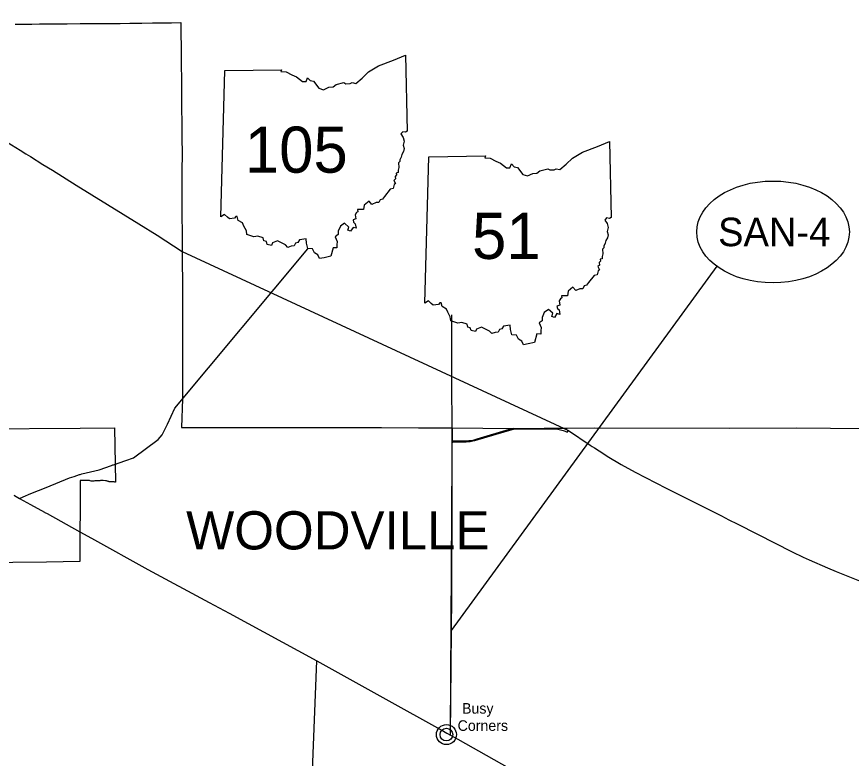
# Model space of a CAD drawing. Extents: x 0 to 798, y 0 to 440.
# Drawn here: x 204.7 to 286.7, y 280.2 to 353 of the extents above; entities that cross this region are included whole.
import ezdxf

# ---------------------------------------------------------------- set-up
doc = ezdxf.new("R2010")
doc.units = 0
for name, color, linetype in [('DV_X_Corp_Line', 7, 'Continuous'), ('GM_X_Corporation_Text', 7, 'Continuous'), ('GM_X_County', 7, 'Continuous'), ('GM_X_Interchange_Ramps', 7, 'Continuous'), ('GM_X_Interstate_Route', 7, 'Continuous'), ('GM_X_State_Route', 7, 'Continuous'), ('GM_X_US_Route', 7, 'Continuous'), ('PV_P_Text', 7, 'Continuous'), ('SH_Data', 7, 'Continuous'), ('SH_Text', 7, 'Continuous')]:
    doc.layers.add(name, color=color, linetype=linetype)

msp = doc.modelspace()

# ---------------------------------------------------------------- linework, layer by layer
at = {"layer": 'DV_X_Corp_Line'}
msp.add_lwpolyline([(200.894, 312.518), (210.921, 312.576), (214.317, 312.612), (214.402, 307.271), (214.372, 307.276), (214.331, 307.284), (214.276, 307.3), (214.135, 307.317), (214.076, 307.308), (214.016, 307.314), (213.964, 307.314), (213.914, 307.31), (213.862, 307.316), (213.836, 307.32), (213.793, 307.328), (213.75, 307.341), (213.687, 307.356), (213.616, 307.374), (213.575, 307.386), (213.504, 307.401), (213.418, 307.41), (213.197, 307.451), (213.12, 307.457), (213.004, 307.45), (212.936, 307.438), (212.874, 307.424), (212.806, 307.412), (212.709, 307.402), (212.651, 307.409), (212.566, 307.415), (212.491, 307.417), (212.419, 307.412), (212.368, 307.409), (212.275, 307.385), (212.216, 307.375), (212.165, 307.376), (212.117, 307.377), (212.059, 307.383), (212.027, 307.392), (211.917, 307.42), (211.833, 307.436), (211.678, 307.442), (211.57, 307.443), (211.518, 307.435), (211.217, 307.441), (211.119, 307.451), (210.94, 307.444), (210.896, 299.491), (207.629, 299.434), (197.628, 299.32)], dxfattribs=at)
for radius in [0.982, 0.623]:
    msp.add_circle((246.914, 282.486), radius, dxfattribs=at)
at = {"layer": 'GM_X_County'}
msp.add_lwpolyline([(204.534, 352.255), (205.062, 352.267), (206.185, 352.282), (206.942, 352.296), (207.459, 352.303), (207.536, 352.298), (207.568, 352.296), (207.693, 352.297), (208.076, 352.304), (208.897, 352.313), (209.643, 352.312), (210.935, 352.324), (211.89, 352.328), (213.73, 352.334), (214.874, 352.345), (215.799, 352.352), (216.236, 352.363), (217.002, 352.375), (218.023, 352.392), (218.741, 352.394), (219.405, 352.397), (219.895, 352.406), (220.816, 352.426), (220.816, 352.378), (220.825, 351.841), (220.835, 351.308), (220.836, 350.856), (220.841, 350.487), (220.843, 350.076), (220.856, 349.132), (220.86, 348.681), (220.869, 347.941), (220.872, 347.16), (220.874, 346.587), (220.878, 345.315), (220.89, 344.166), (220.906, 342.4), (220.91, 341.662), (220.923, 340.759), (220.939, 339.936), (220.94, 339.162), (220.928, 338.215), (220.922, 336.65), (220.926, 335.631), (220.934, 333.043), (220.939, 332.183), (220.94, 331.403), (220.948, 330.561), (220.949, 330.349), (220.95, 330.138), (220.95, 329.929), (220.955, 329.431), (220.957, 328.895), (220.959, 328.567), (220.972, 327.295), (220.975, 327.011), (220.978, 326.597), (220.983, 325.982), (220.985, 325.694), (220.98, 325.078), (220.98, 324.586), (220.978, 323.847), (220.979, 322.369), (220.983, 321.22), (220.985, 319.66), (220.992, 316.992), (220.989, 315.883), (220.992, 315.739), (220.997, 315.474), (220.886, 312.654), (221.725, 312.652), (234.256, 312.66), (240.543, 312.637), (244.18, 312.615), (247.499, 312.607), (253.476, 312.555), (253.781, 312.555), (254.857, 312.564), (256.582, 312.582), (258.496, 312.6), (258.782, 312.601), (261.475, 312.609), (274.69, 312.588), (281.301, 312.63), (287.982, 312.538)], dxfattribs=at)
at = {"layer": 'GM_X_Interchange_Ramps'}
for points in [[(253.476, 312.555), (253.312, 312.523), (253.207, 312.499), (253.075, 312.458), (249.909, 311.496), (249.493, 311.389), (249.305, 311.351), (249.116, 311.332), (248.858, 311.307), (247.619, 311.3), (247.478, 311.301)], [(247.478, 311.238), (247.612, 311.238), (247.984, 311.244), (248.852, 311.25), (249.091, 311.263), (249.236, 311.282), (249.38, 311.307), (249.506, 311.332), (249.707, 311.389), (251.79, 311.993), (253.369, 312.452), (253.514, 312.484), (253.763, 312.511), (254.857, 312.515), (256.342, 312.528), (257.51, 312.516), (257.854, 312.479), (258.12, 312.427), (258.369, 312.355), (258.594, 312.282), (258.788, 312.2), (258.896, 312.348)], [(256.342, 312.528), (256.413, 312.545), (256.471, 312.557), (256.539, 312.573), (256.582, 312.582)]]:
    msp.add_lwpolyline(points, dxfattribs=at)
at = {"layer": 'GM_X_Interstate_Route'}
msp.add_line((220.95, 329.929), (258.896, 312.348), dxfattribs=at)
for points in [[(169.37, 361.381), (188.305, 350.222), (191.786, 348.073), (192.461, 347.656), (193.36, 347.1), (194.029, 346.683), (194.194, 346.58), (196.95, 344.878), (203.348, 340.924), (205.031, 339.878), (205.597, 339.535), (206.049, 339.255), (207.277, 338.491), (208.206, 337.922), (210.546, 336.458), (216.705, 332.657), (218.504, 331.547), (220.95, 329.929)], [(258.496, 312.6), (258.896, 312.348), (261.047, 310.919), (261.238, 310.791)], [(261.238, 310.791), (261.46, 310.641), (262.37, 310.051), (262.704, 309.839), (264.069, 309.025), (265.461, 308.265), (268.513, 306.708), (271.58, 305.16), (273.929, 303.964), (274.655, 303.595), (275.465, 303.195), (277.466, 302.175), (280.881, 300.442), (281.947, 299.923), (282.548, 299.644), (284.366, 298.873), (285.22, 298.519), (287.991, 297.39), (288.399, 297.235), (291.708, 295.905), (297.704, 293.477), (299.536, 292.733), (301.251, 292.036)]]:
    msp.add_lwpolyline(points, dxfattribs=at)
at = {"layer": 'GM_X_State_Route'}
for points in [[(214.195, 308.988), (215.426, 309.4), (216.172, 309.683), (218.583, 311.469), (218.993, 311.938), (219.522, 312.986), (220.237, 314.562), (233.294, 330.217)], [(247.314, 282.433), (247.432, 296.051), (247.489, 305.985), (247.451, 323.715)], [(247.481, 310.056), (247.478, 311.238), (247.478, 311.301), (247.499, 312.607)], [(210.888, 308.03), (210.919, 308.04), (211.091, 308.095), (212.781, 308.501), (214.02, 308.929), (214.145, 308.971), (214.195, 308.988)], [(204.973, 305.688), (205.316, 305.83), (206.098, 306.153), (207.592, 306.769), (209.877, 307.706), (210.33, 307.851), (210.853, 308.019), (210.888, 308.03)], [(233.688, 276.598), (233.761, 278.953), (234.187, 289.718)]]:
    msp.add_lwpolyline(points, dxfattribs=at)
at = {"layer": 'GM_X_US_Route'}
for points in [[(204.415, 306.004), (204.487, 305.964), (204.973, 305.688), (206.04, 305.097), (207.44, 304.321), (207.457, 304.312)], [(207.457, 304.312), (207.675, 304.191), (210.9, 302.407), (210.9, 302.406)], [(210.9, 302.406), (212.052, 301.769), (212.052, 301.769)], [(212.052, 301.769), (217.58, 298.71), (223.615, 295.453), (225.569, 294.415), (234.187, 289.718), (240.661, 286.132), (246.614, 282.822), (246.614, 282.822)], [(246.614, 282.822), (246.964, 282.627)], [(246.964, 282.627), (247.314, 282.433)], [(247.314, 282.433), (248.019, 282.038)], [(248.019, 282.038), (254.368, 278.485), (261.264, 274.686), (264.516, 272.877), (271.054, 269.205), (274.346, 267.401), (277.607, 265.533), (283.14, 262.329), (283.955, 261.858), (284.816, 261.359), (285.651, 260.876), (285.787, 260.797)]]:
    msp.add_lwpolyline(points, dxfattribs=at)
at = {"layer": 'PV_P_Text'}
for p, q in [((224.752, 333.342), (225.154, 347.705)), ((224.752, 333.342), (225.154, 347.705)), ((244.789, 324.872), (245.19, 339.234)), ((244.789, 324.872), (245.19, 339.234))]:
    msp.add_line(p, q, dxfattribs=at)
for points in [[(225.154, 347.705), (230.727, 347.798), (230.64, 347.624), (231.166, 347.588), (231.724, 347.281), (232.196, 347.088), (232.774, 346.631), (233.12, 346.636), (233.266, 347.011), (233.531, 346.722), (233.845, 346.67), (234.388, 345.982), (234.837, 345.834), (235.374, 346.069), (235.776, 346.108), (236.069, 346.341), (236.834, 346.54), (237.047, 346.421), (237.452, 346.445), (237.655, 346.533), (238.009, 346.454), (238.63, 346.976), (239.27, 347.592), (240.254, 348.173), (241.724, 348.723), (242.887, 349.216), (243.055, 341.762)], [(225.154, 347.705), (230.727, 347.798), (230.64, 347.624), (231.166, 347.588), (231.724, 347.281), (232.196, 347.088), (232.774, 346.631), (233.12, 346.636), (233.266, 347.011), (233.531, 346.722), (233.845, 346.67), (234.388, 345.982), (234.837, 345.834), (235.374, 346.069), (235.776, 346.108), (236.069, 346.341), (236.834, 346.54), (237.047, 346.421), (237.452, 346.445), (237.655, 346.533), (238.009, 346.454), (238.63, 346.976), (239.27, 347.592), (240.254, 348.173), (241.724, 348.723), (242.887, 349.216), (243.055, 341.762)], [(243.055, 341.762), (242.883, 341.658), (242.616, 341.707), (242.436, 341.498), (242.659, 341.149), (242.764, 340.781), (242.671, 340.375), (242.762, 340.04), (242.7, 339.759), (242.532, 339.48), (242.474, 339.214), (242.332, 338.934), (242.343, 338.777), (242.207, 338.653), (242.232, 338.187), (242.163, 337.928), (242.187, 337.705), (241.966, 337.647), (242.017, 337.463), (241.876, 337.321), (241.906, 337.076), (241.747, 336.92), (241.902, 336.607), (241.778, 336.508), (241.675, 336.128), (241.392, 336.051), (240.825, 335.355), (240.625, 335.092), (240.4, 335.027), (240.276, 334.756), (240, 334.755), (239.581, 334.568), (239.311, 334.891), (238.837, 334.503), (238.782, 334.055), (238.182, 334.069), (238.206, 333.843), (238.072, 333.777), (237.95, 333.55), (238.021, 333.147), (237.74, 333.044), (237.774, 332.81), (237.954, 332.667), (238.034, 332.22), (237.736, 332.31), (237.491, 331.933), (237.24, 332.022), (237.322, 332.341), (236.898, 332.725), (236.496, 332.418), (236.287, 331.926), (236.284, 331.596), (235.985, 331.396), (236.177, 330.929), (236.142, 330.607), (236.148, 330.302), (235.774, 330.312), (235.547, 329.488)], [(243.055, 341.762), (242.883, 341.658), (242.616, 341.707), (242.436, 341.498), (242.659, 341.149), (242.764, 340.781), (242.671, 340.375), (242.762, 340.04), (242.7, 339.759), (242.532, 339.48), (242.474, 339.214), (242.332, 338.934), (242.343, 338.777), (242.207, 338.653), (242.232, 338.187), (242.163, 337.928), (242.187, 337.705), (241.966, 337.647), (242.017, 337.463), (241.876, 337.321), (241.906, 337.076), (241.747, 336.92), (241.902, 336.607), (241.778, 336.508), (241.675, 336.128), (241.392, 336.051), (240.825, 335.355), (240.625, 335.092), (240.4, 335.027), (240.276, 334.756), (240, 334.755), (239.581, 334.568), (239.311, 334.891), (238.837, 334.503), (238.782, 334.055), (238.182, 334.069), (238.206, 333.843), (238.072, 333.777), (237.95, 333.55), (238.021, 333.147), (237.74, 333.044), (237.774, 332.81), (237.954, 332.667), (238.034, 332.22), (237.736, 332.31), (237.491, 331.933), (237.24, 332.022), (237.322, 332.341), (236.898, 332.725), (236.496, 332.418), (236.287, 331.926), (236.284, 331.596), (235.985, 331.396), (236.177, 330.929), (236.142, 330.607), (236.148, 330.302), (235.774, 330.312), (235.547, 329.488)], [(245.19, 339.234), (250.763, 339.328), (250.676, 339.154), (251.202, 339.118), (251.761, 338.811), (252.233, 338.617), (252.811, 338.161), (253.156, 338.166), (253.303, 338.54), (253.567, 338.251), (253.882, 338.2), (254.425, 337.512), (254.873, 337.363), (255.41, 337.599), (255.812, 337.638), (256.105, 337.87), (256.87, 338.07), (257.083, 337.95), (257.488, 337.974), (257.692, 338.063), (258.045, 337.984), (258.667, 338.506), (259.307, 339.122), (260.291, 339.703), (261.761, 340.253), (262.923, 340.746), (263.091, 333.292)], [(245.19, 339.234), (250.763, 339.328), (250.676, 339.154), (251.202, 339.118), (251.761, 338.811), (252.233, 338.617), (252.811, 338.161), (253.156, 338.166), (253.303, 338.54), (253.567, 338.251), (253.882, 338.2), (254.425, 337.512), (254.873, 337.363), (255.41, 337.599), (255.812, 337.638), (256.105, 337.87), (256.87, 338.07), (257.083, 337.95), (257.488, 337.974), (257.692, 338.063), (258.045, 337.984), (258.667, 338.506), (259.307, 339.122), (260.291, 339.703), (261.761, 340.253), (262.923, 340.746), (263.091, 333.292)], [(235.547, 329.488), (234.897, 329.33), (234.445, 329.236), (234.286, 329.61), (233.963, 329.808), (233.753, 330.185), (233.29, 330.236), (233.18, 330.754), (233.128, 331.174), (232.494, 331.071), (232.32, 330.814), (232.095, 330.745), (231.965, 330.486), (231.658, 330.464), (231.33, 330.342), (231.114, 330.596), (230.576, 330.851), (230.334, 330.983), (229.827, 330.778), (229.719, 330.536), (229.316, 330.643), (229.222, 330.913), (228.977, 330.994), (228.924, 331.28), (228.402, 331.432), (228.003, 331.371), (227.3, 331.602), (227.257, 331.978), (227.017, 332.437), (226.892, 332.755), (226.448, 332.998), (226.358, 333.377), (226.215, 333.366), (226.085, 333.212), (225.591, 333.141), (225.394, 333.296), (225.118, 333.56), (224.752, 333.342)], [(235.547, 329.488), (234.897, 329.33), (234.445, 329.236), (234.286, 329.61), (233.963, 329.808), (233.753, 330.185), (233.29, 330.236), (233.18, 330.754), (233.128, 331.174), (232.494, 331.071), (232.32, 330.814), (232.095, 330.745), (231.965, 330.486), (231.658, 330.464), (231.33, 330.342), (231.114, 330.596), (230.576, 330.851), (230.334, 330.983), (229.827, 330.778), (229.719, 330.536), (229.316, 330.643), (229.222, 330.913), (228.977, 330.994), (228.924, 331.28), (228.402, 331.432), (228.003, 331.371), (227.3, 331.602), (227.257, 331.978), (227.017, 332.437), (226.892, 332.755), (226.448, 332.998), (226.358, 333.377), (226.215, 333.366), (226.085, 333.212), (225.591, 333.141), (225.394, 333.296), (225.118, 333.56), (224.752, 333.342)], [(263.091, 333.292), (262.92, 333.188), (262.652, 333.237), (262.473, 333.028), (262.695, 332.679), (262.8, 332.31), (262.707, 331.904), (262.799, 331.569), (262.736, 331.289), (262.569, 331.01), (262.51, 330.744), (262.368, 330.464), (262.38, 330.307), (262.244, 330.182), (262.268, 329.716), (262.2, 329.458), (262.223, 329.235), (262.003, 329.177), (262.053, 328.993), (261.913, 328.85), (261.943, 328.606), (261.784, 328.45), (261.938, 328.137), (261.814, 328.038), (261.711, 327.657), (261.428, 327.58), (260.861, 326.885), (260.661, 326.622), (260.437, 326.556), (260.313, 326.286), (260.036, 326.285), (259.618, 326.098), (259.347, 326.42), (258.873, 326.032), (258.818, 325.585), (258.219, 325.599), (258.242, 325.372), (258.109, 325.306), (257.987, 325.08), (258.057, 324.677), (257.777, 324.574), (257.811, 324.34), (257.991, 324.197), (258.07, 323.749), (257.772, 323.84), (257.528, 323.463), (257.277, 323.552), (257.359, 323.871), (256.934, 324.255), (256.533, 323.947), (256.323, 323.456), (256.321, 323.125), (256.021, 322.925), (256.213, 322.458), (256.178, 322.137), (256.184, 321.831), (255.81, 321.842), (255.583, 321.017)], [(263.091, 333.292), (262.92, 333.188), (262.652, 333.237), (262.473, 333.028), (262.695, 332.679), (262.8, 332.31), (262.707, 331.904), (262.799, 331.569), (262.736, 331.289), (262.569, 331.01), (262.51, 330.744), (262.368, 330.464), (262.38, 330.307), (262.244, 330.182), (262.268, 329.716), (262.2, 329.458), (262.223, 329.235), (262.003, 329.177), (262.053, 328.993), (261.913, 328.85), (261.943, 328.606), (261.784, 328.45), (261.938, 328.137), (261.814, 328.038), (261.711, 327.657), (261.428, 327.58), (260.861, 326.885), (260.661, 326.622), (260.437, 326.556), (260.313, 326.286), (260.036, 326.285), (259.618, 326.098), (259.347, 326.42), (258.873, 326.032), (258.818, 325.585), (258.219, 325.599), (258.242, 325.372), (258.109, 325.306), (257.987, 325.08), (258.057, 324.677), (257.777, 324.574), (257.811, 324.34), (257.991, 324.197), (258.07, 323.749), (257.772, 323.84), (257.528, 323.463), (257.277, 323.552), (257.359, 323.871), (256.934, 324.255), (256.533, 323.947), (256.323, 323.456), (256.321, 323.125), (256.021, 322.925), (256.213, 322.458), (256.178, 322.137), (256.184, 321.831), (255.81, 321.842), (255.583, 321.017)], [(255.583, 321.017), (254.933, 320.86), (254.482, 320.765), (254.323, 321.14), (254, 321.337), (253.79, 321.714), (253.326, 321.766), (253.216, 322.284), (253.164, 322.704), (252.531, 322.6), (252.357, 322.343), (252.132, 322.274), (252.001, 322.015), (251.695, 321.994), (251.366, 321.872), (251.151, 322.125), (250.612, 322.381), (250.37, 322.512), (249.864, 322.308), (249.755, 322.066), (249.352, 322.173), (249.258, 322.442), (249.014, 322.523), (248.96, 322.809), (248.439, 322.962), (248.04, 322.901), (247.336, 323.131), (247.294, 323.508), (247.054, 323.966), (246.929, 324.285), (246.484, 324.528), (246.394, 324.907), (246.252, 324.895), (246.122, 324.742), (245.628, 324.671), (245.43, 324.826), (245.154, 325.09), (244.789, 324.872)], [(255.583, 321.017), (254.933, 320.86), (254.482, 320.765), (254.323, 321.14), (254, 321.337), (253.79, 321.714), (253.326, 321.766), (253.216, 322.284), (253.164, 322.704), (252.531, 322.6), (252.357, 322.343), (252.132, 322.274), (252.001, 322.015), (251.695, 321.994), (251.366, 321.872), (251.151, 322.125), (250.612, 322.381), (250.37, 322.512), (249.864, 322.308), (249.755, 322.066), (249.352, 322.173), (249.258, 322.442), (249.014, 322.523), (248.96, 322.809), (248.439, 322.962), (248.04, 322.901), (247.336, 323.131), (247.294, 323.508), (247.054, 323.966), (246.929, 324.285), (246.484, 324.528), (246.394, 324.907), (246.252, 324.895), (246.122, 324.742), (245.628, 324.671), (245.43, 324.826), (245.154, 325.09), (244.789, 324.872)]]:
    msp.add_lwpolyline(points, dxfattribs=at)
at = {"layer": 'SH_Data'}
msp.add_line((273.466, 328.487), (247.378, 292.723), dxfattribs=at)
msp.add_ellipse((279.002, 331.86), major_axis=(7.5, 0), ratio=0.666667, dxfattribs=at)
at = {"layer": 'SH_Text'}
msp.add_lwpolyline([(247.316, 282.695), (247.482, 309.609), (247.499, 312.607)], dxfattribs=at)

# ---------------------------------------------------------------- texts
at = {"layer": 'DV_X_Corp_Line'}
for s, p in [('Busy', (248.446, 284.543)), ('Corners', (248.014, 282.852))]:
    msp.add_text(s, height=1.0417, rotation=0.00001, dxfattribs=at).set_placement(p)
at = {"layer": 'GM_X_Corporation_Text'}
msp.add_text('WOODVILLE', height=3.75, rotation=0.00001, dxfattribs=at).set_placement((221.337, 300.676))
at = {"layer": 'PV_P_Text'}
for s, p in [('105', (227.114, 337.679)), ('51', (249.432, 329.209))]:
    msp.add_text(s, height=4.5281, dxfattribs=at).set_placement(p)
at = {"layer": 'SH_Data'}
msp.add_text('SAN-4', height=2.8, dxfattribs=at).set_placement((273.604, 330.46))

doc.saveas('drawing.dxf')
